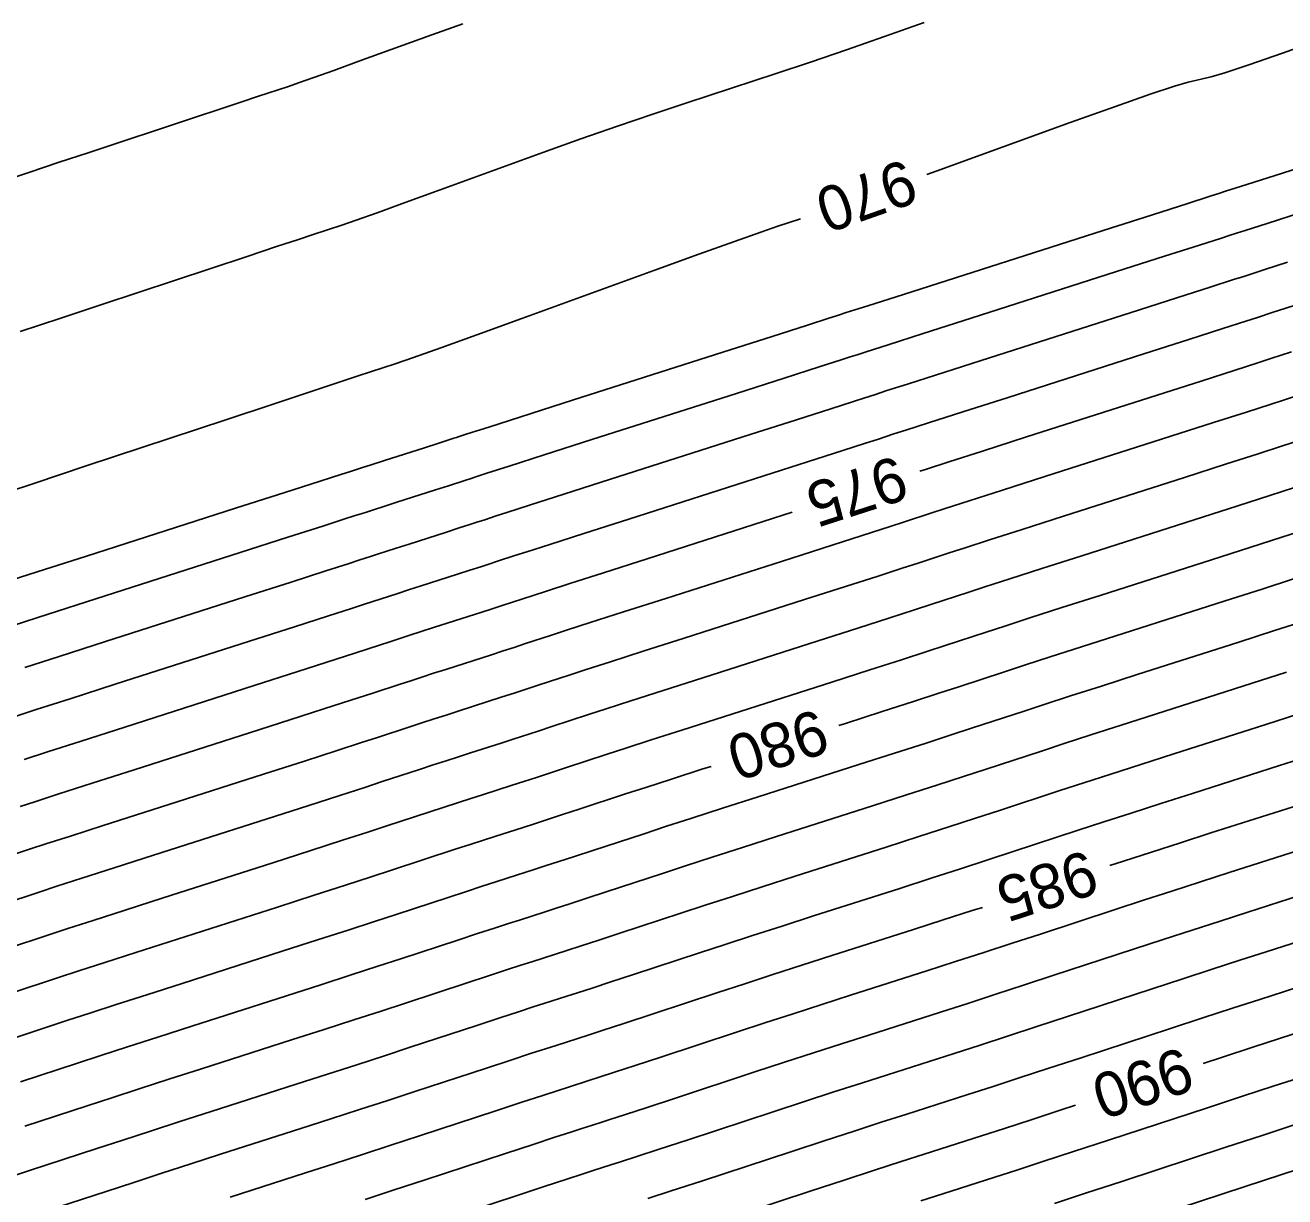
# Model space of a CAD drawing. Extents: x 2175772 to 2185556, y 721391 to 722853.
# Drawn here: x 2178902 to 2178980.9, y 721896.5 to 721969.8 of the extents above; entities that cross this region are included whole.
import ezdxf

# ---------------------------------------------------------------- set-up
doc = ezdxf.new("R2010")
doc.units = 0
doc.layers.add('DT_X_Contour_Major', color=7, linetype='Continuous')
doc.layers.add('DT_X_Contour_Minor', color=7, linetype='Continuous')

msp = doc.modelspace()

# ---------------------------------------------------------------- linework, layer by layer
at = {"layer": 'DT_X_Contour_Major'}
for points in [[(2178958.479, 721960.501), (2178959.055, 721960.709), (2178967.461, 721963.751), (2178970.287, 721964.765), (2178972.46, 721965.525), (2178973.98, 721966.032), (2178974.847, 721966.285), (2178976.29, 721966.623), (2178977.147, 721966.871), (2178978.636, 721967.362), (2178980.756, 721968.095), (2178983.507, 721969.072)], [(2178895.939, 721938.964), (2178902.542, 721941.15), (2178905.826, 721942.238), (2178914.565, 721945.131), (2178917.541, 721946.117), (2178919.915, 721946.903), (2178922.857, 721947.877), (2178925.175, 721948.644), (2178926.323, 721949.037), (2178928.03, 721949.64), (2178930.294, 721950.454), (2178933.117, 721951.478), (2178941.388, 721954.488), (2178944.199, 721955.507), (2178946.428, 721956.307), (2178948.074, 721956.888), (2178949.139, 721957.25), (2178950.556, 721957.712)], [(2178958.045, 721941.917), (2178958.393, 721942.029), (2178959.859, 721942.501), (2178961.967, 721943.177), (2178964.718, 721944.058), (2178972.909, 721946.678), (2178975.657, 721947.558), (2178979.214, 721948.7), (2178980.023, 721948.963), (2178981.318, 721949.388)], [(2178901.934, 721923.862), (2178903.409, 721924.338), (2178905.51, 721925.013), (2178908.24, 721925.889), (2178916.354, 721928.49), (2178919.082, 721929.365), (2178922.652, 721930.514), (2178923.493, 721930.787), (2178924.898, 721931.248), (2178925.461, 721931.432), (2178926.096, 721931.638), (2178926.804, 721931.867), (2178927.583, 721932.117), (2178929.759, 721932.815), (2178930.538, 721933.065), (2178931.243, 721933.292), (2178931.874, 721933.497), (2178933.82, 721934.135), (2178934.657, 721934.407), (2178936.127, 721934.88), (2178938.231, 721935.555), (2178940.969, 721936.431), (2178950.051, 721939.338)], [(2178952.958, 721925.987), (2178953.371, 721926.119), (2178955.678, 721926.858), (2178957.632, 721927.487), (2178959.233, 721928.005), (2178960.482, 721928.412), (2178963.343, 721929.351), (2178964.594, 721929.759), (2178966.202, 721930.279), (2178968.168, 721930.911), (2178977.158, 721933.789), (2178979.478, 721934.532), (2178981.437, 721935.162)], [(2178901.12, 721909.223), (2178904.086, 721910.197), (2178905.368, 721910.615), (2178906.987, 721911.14), (2178908.946, 721911.771), (2178917.817, 721914.616), (2178920.112, 721915.353), (2178922.066, 721915.983), (2178923.68, 721916.505), (2178924.953, 721916.921), (2178928.942, 721918.23), (2178929.88, 721918.535), (2178930.707, 721918.804), (2178931.424, 721919.035), (2178933.19, 721919.601), (2178933.905, 721919.831), (2178934.728, 721920.098), (2178935.658, 721920.402), (2178936.695, 721920.741), (2178939.605, 721921.696), (2178940.869, 721922.109), (2178942.482, 721922.63), (2178944.443, 721923.261), (2178944.958, 721923.426)], [(2178981.408, 721920.9), (2178976.262, 721919.253), (2178974.368, 721918.645), (2178972.546, 721918.057), (2178970.796, 721917.489), (2178969.936, 721917.208)], [(2178961.953, 721914.595), (2178961.318, 721914.388), (2178959.508, 721913.804), (2178957.63, 721913.202), (2178952.534, 721911.571), (2178950.654, 721910.968), (2178948.837, 721910.381), (2178947.082, 721909.811), (2178945.39, 721909.257), (2178939.442, 721907.306), (2178938.213, 721906.904), (2178937.273, 721906.598), (2178936.62, 721906.387), (2178935.265, 721905.952), (2178933.663, 721905.432), (2178932.423, 721905.027), (2178930.891, 721904.524), (2178926.414, 721903.055), (2178924.709, 721902.497), (2178922.951, 721901.926), (2178921.142, 721901.341), (2178919.279, 721900.742), (2178914.244, 721899.128), (2178912.381, 721898.529), (2178910.566, 721897.942), (2178908.801, 721897.368), (2178907.086, 721896.807), (2178902.576, 721895.326)], [(2178982.034, 721906.851), (2178980.568, 721906.38), (2178978.889, 721905.836), (2178976.997, 721905.219), (2178975.777, 721904.819)], [(2178967.795, 721902.201), (2178966.889, 721901.904), (2178965.004, 721901.29), (2178963.337, 721900.75), (2178961.889, 721900.284), (2178958.317, 721899.141), (2178956.866, 721898.674), (2178955.192, 721898.132), (2178953.295, 721897.513), (2178951.175, 721896.819), (2178945.224, 721894.866)]]:
    msp.add_lwpolyline(points, dxfattribs=at)
at = {"layer": 'DT_X_Contour_Minor'}
for points in [[(2178900.456, 721960.043), (2178902.295, 721960.652), (2178904.128, 721961.259), (2178905.954, 721961.863), (2178912.615, 721964.069), (2178914.264, 721964.615), (2178915.58, 721965.05), (2178916.562, 721965.376), (2178917.21, 721965.59), (2178918.494, 721966.015), (2178919.13, 721966.233), (2178920.076, 721966.567), (2178921.331, 721967.018), (2178922.894, 721967.585), (2178927.477, 721969.253), (2178929.408, 721969.94)], [(2178901.688, 721950.659), (2178904.248, 721951.507), (2178906.799, 721952.352), (2178915.903, 721955.366), (2178917.747, 721955.977), (2178919.124, 721956.432), (2178920.034, 721956.734), (2178921.835, 721957.33), (2178922.727, 721957.635), (2178924.053, 721958.104), (2178925.812, 721958.736), (2178928.006, 721959.531), (2178934.433, 721961.87), (2178936.804, 721962.723), (2178939.096, 721963.528), (2178941.31, 721964.284), (2178943.446, 721964.992), (2178949.037, 721966.816), (2178951.189, 721967.529), (2178953.453, 721968.301), (2178955.827, 721969.132), (2178958.314, 721970.023)], [(2178900.545, 721934.896), (2178902.762, 721935.607), (2178905.838, 721936.593), (2178915.184, 721939.589), (2178918.258, 721940.575), (2178920.474, 721941.286), (2178921.829, 721941.72), (2178922.325, 721941.88), (2178922.501, 721941.938), (2178923.07, 721942.121), (2178923.681, 721942.317), (2178924.511, 721942.583), (2178927.014, 721943.386), (2178927.843, 721943.651), (2178928.846, 721943.974), (2178929.02, 721944.03), (2178929.192, 721944.086), (2178929.687, 721944.245), (2178931.044, 721944.679), (2178936.343, 721946.375), (2178945.706, 721949.371), (2178948.784, 721950.356), (2178950.996, 721951.064), (2178952.343, 721951.495), (2178952.823, 721951.649), (2178952.949, 721951.691), (2178953.431, 721951.846), (2178954.784, 721952.279), (2178957.007, 721952.99), (2178969.509, 721956.99), (2178972.6, 721957.979), (2178974.817, 721958.688), (2178976.159, 721959.118), (2178976.626, 721959.268), (2178976.707, 721959.294), (2178977.177, 721959.445), (2178978.525, 721959.876), (2178980.752, 721960.589), (2178983.858, 721961.582)], [(2178901.261, 721932.256), (2178903.449, 721932.958), (2178906.438, 721933.917), (2178915.476, 721936.814), (2178918.464, 721937.773), (2178920.651, 721938.474), (2178922.035, 721938.919), (2178922.617, 721939.107), (2178923.101, 721939.265), (2178923.373, 721939.354), (2178923.827, 721939.5), (2178924.462, 721939.704), (2178925.279, 721939.967), (2178927.7, 721940.743), (2178928.517, 721941.005), (2178929.603, 721941.354), (2178929.873, 721941.442), (2178930.349, 721941.598), (2178930.929, 721941.785), (2178932.315, 721942.229), (2178934.505, 721942.931), (2178937.499, 721943.889), (2178946.558, 721946.788), (2178949.55, 721947.746), (2178951.734, 721948.445), (2178953.108, 721948.885), (2178953.674, 721949.068), (2178954.104, 721949.209), (2178954.672, 721949.392), (2178956.053, 721949.834), (2178958.247, 721950.537), (2178961.255, 721951.499), (2178970.359, 721954.412), (2178973.364, 721955.374), (2178975.552, 721956.074), (2178976.923, 721956.513), (2178977.475, 721956.691), (2178977.86, 721956.817), (2178978.415, 721956.996), (2178979.792, 721957.437), (2178981.99, 721958.141)], [(2178901.977, 721929.617), (2178904.136, 721930.31), (2178907.039, 721931.241), (2178915.769, 721934.04), (2178918.67, 721934.97), (2178920.828, 721935.663), (2178922.241, 721936.117), (2178922.909, 721936.333), (2178923.7, 721936.593), (2178924.069, 721936.713), (2178924.583, 721936.88), (2178925.243, 721937.092), (2178926.047, 721937.35), (2178928.386, 721938.1), (2178929.19, 721938.358), (2178929.848, 721938.57), (2178930.36, 721938.735), (2178930.726, 721938.854), (2178931.506, 721939.11), (2178932.172, 721939.326), (2178933.586, 721939.78), (2178935.747, 721940.472), (2178938.656, 721941.403), (2178947.409, 721944.204), (2178950.316, 721945.135), (2178952.471, 721945.825), (2178953.874, 721946.275), (2178954.525, 721946.486), (2178955.259, 721946.726), (2178955.912, 721946.937), (2178957.321, 721947.39), (2178962.409, 721949.019), (2178971.209, 721951.834), (2178974.129, 721952.769), (2178976.288, 721953.46), (2178977.686, 721953.909), (2178978.325, 721954.115), (2178979.012, 721954.341), (2178979.653, 721954.548), (2178981.058, 721954.998)], [(2178901.247, 721926.512), (2178902.693, 721926.977), (2178904.823, 721927.661), (2178907.639, 721928.565), (2178916.061, 721931.265), (2178918.876, 721932.168), (2178921.005, 721932.851), (2178922.446, 721933.315), (2178923.201, 721933.56), (2178924.299, 721933.921), (2178924.765, 721934.073), (2178925.34, 721934.259), (2178926.023, 721934.479), (2178926.815, 721934.734), (2178929.073, 721935.457), (2178929.864, 721935.711), (2178930.545, 721935.931), (2178931.117, 721936.116), (2178931.578, 721936.267), (2178932.663, 721936.623), (2178933.414, 721936.866), (2178934.856, 721937.33), (2178936.989, 721938.013), (2178939.812, 721938.917), (2178948.261, 721941.621), (2178953.208, 721943.205), (2178954.639, 721943.665), (2178955.376, 721943.904), (2178956.414, 721944.244), (2178957.152, 721944.483), (2178958.59, 721944.945), (2178960.727, 721945.63), (2178963.563, 721946.538), (2178972.059, 721949.256), (2178974.893, 721950.163), (2178977.023, 721950.846), (2178978.45, 721951.305), (2178979.174, 721951.539), (2178980.165, 721951.864), (2178980.891, 721952.099), (2178982.324, 721952.56)], [(2178901.687, 721920.909), (2178902.621, 721921.213), (2178904.124, 721921.698), (2178906.197, 721922.365), (2178908.84, 721923.212), (2178916.646, 721925.715), (2178919.288, 721926.563), (2178921.359, 721927.228), (2178922.858, 721927.712), (2178923.785, 721928.014), (2178925.498, 721928.576), (2178926.157, 721928.792), (2178926.853, 721929.018), (2178927.585, 721929.254), (2178928.352, 721929.501), (2178931.211, 721930.418), (2178931.94, 721930.653), (2178932.631, 721930.878), (2178933.284, 721931.092), (2178934.977, 721931.647), (2178935.899, 721931.947), (2178937.398, 721932.43), (2178939.474, 721933.096), (2178942.125, 721933.945), (2178949.965, 721936.454), (2178952.614, 721937.302), (2178956.171, 721938.445), (2178957.078, 721938.74), (2178958.723, 721939.28), (2178959.633, 721939.575), (2178961.128, 721940.057), (2178963.207, 721940.724), (2178965.872, 721941.577), (2178973.759, 721944.101), (2178976.421, 721944.953), (2178978.495, 721945.618), (2178979.978, 721946.096), (2178980.872, 721946.386), (2178982.471, 721946.911)], [(2178900.246, 721917.561), (2178902.287, 721918.231), (2178903.307, 721918.563), (2178904.84, 721919.058), (2178906.884, 721919.716), (2178909.441, 721920.536), (2178916.939, 721922.94), (2178919.494, 721923.76), (2178921.536, 721924.417), (2178923.063, 721924.91), (2178924.077, 721925.241), (2178926.097, 721925.903), (2178926.854, 721926.151), (2178927.61, 721926.397), (2178928.365, 721926.642), (2178929.12, 721926.884), (2178931.885, 721927.771), (2178932.637, 721928.015), (2178933.388, 721928.259), (2178934.137, 721928.504), (2178936.134, 721929.159), (2178937.142, 721929.487), (2178938.669, 721929.98), (2178940.716, 721930.637), (2178943.282, 721931.459), (2178950.816, 721933.87), (2178953.38, 721934.691), (2178955.42, 721935.346), (2178956.936, 721935.835), (2178957.929, 721936.158), (2178959.878, 721936.798), (2178960.873, 721937.121), (2178962.396, 721937.612), (2178964.447, 721938.271), (2178967.027, 721939.097), (2178974.609, 721941.523), (2178977.186, 721942.348), (2178979.23, 721943.004), (2178980.742, 721943.492), (2178981.722, 721943.81)], [(2178900.538, 721914.782), (2178902.886, 721915.553), (2178903.994, 721915.914), (2178905.556, 721916.419), (2178907.571, 721917.068), (2178910.041, 721917.86), (2178919.7, 721920.958), (2178921.712, 721921.606), (2178923.269, 721922.109), (2178924.369, 721922.467), (2178926.696, 721923.231), (2178927.55, 721923.511), (2178928.366, 721923.777), (2178929.146, 721924.029), (2178929.888, 721924.268), (2178931.817, 721924.886), (2178932.558, 721925.125), (2178934.144, 721925.64), (2178934.99, 721925.917), (2178937.291, 721926.672), (2178938.384, 721927.028), (2178939.94, 721927.53), (2178941.958, 721928.179), (2178944.438, 721928.973), (2178951.668, 721931.287), (2178954.146, 721932.08), (2178956.157, 721932.726), (2178957.702, 721933.225), (2178958.78, 721933.576), (2178961.033, 721934.315), (2178962.113, 721934.667), (2178963.665, 721935.168), (2178965.687, 721935.818), (2178968.181, 721936.616), (2178977.95, 721939.743), (2178979.966, 721940.39), (2178981.506, 721940.887)], [(2178900.829, 721912.003), (2178903.486, 721912.875), (2178904.681, 721913.265), (2178906.272, 721913.779), (2178908.259, 721914.419), (2178910.641, 721915.184), (2178917.524, 721917.391), (2178919.906, 721918.155), (2178921.889, 721918.794), (2178923.475, 721919.307), (2178924.661, 721919.694), (2178927.295, 721920.559), (2178928.246, 721920.87), (2178929.926, 721921.416), (2178930.656, 721921.651), (2178932.503, 721922.244), (2178933.232, 721922.478), (2178934.031, 721922.737), (2178934.901, 721923.021), (2178935.843, 721923.329), (2178938.448, 721924.184), (2178939.627, 721924.568), (2178941.211, 721925.08), (2178943.201, 721925.72), (2178952.52, 721928.703), (2178954.912, 721929.469), (2178956.894, 721930.107), (2178958.467, 721930.615), (2178959.631, 721930.994), (2178962.188, 721931.833), (2178963.354, 721932.213), (2178964.934, 721932.724), (2178966.927, 721933.365), (2178969.335, 721934.136), (2178976.308, 721936.367), (2178978.714, 721937.138), (2178980.701, 721937.776), (2178982.27, 721938.283)], [(2178901.411, 721906.444), (2178904.686, 721907.519), (2178906.054, 721907.966), (2178907.703, 721908.5), (2178909.633, 721909.122), (2178911.842, 721909.832), (2178918.109, 721911.841), (2178920.318, 721912.55), (2178922.243, 721913.171), (2178923.886, 721913.704), (2178925.246, 721914.148), (2178928.494, 721915.214), (2178929.638, 721915.589), (2178930.636, 721915.915), (2178931.488, 721916.191), (2178932.192, 721916.418), (2178933.876, 721916.958), (2178934.579, 721917.185), (2178935.425, 721917.459), (2178936.415, 721917.782), (2178937.548, 721918.154), (2178940.762, 721919.208), (2178942.112, 721919.649), (2178943.753, 721920.181), (2178945.685, 721920.803), (2178947.908, 721921.515), (2178954.223, 721923.536), (2178956.444, 721924.248), (2178958.369, 721924.867), (2178959.999, 721925.395), (2178961.333, 721925.83), (2178964.498, 721926.869), (2178965.834, 721927.305), (2178967.471, 721927.835), (2178969.408, 721928.458), (2178971.644, 721929.175), (2178978.008, 721931.211), (2178980.243, 721931.927), (2178982.172, 721932.548)], [(2178901.703, 721903.664), (2178905.286, 721904.841), (2178906.741, 721905.316), (2178908.419, 721905.861), (2178910.32, 721906.474), (2178912.443, 721907.156), (2178920.524, 721909.748), (2178922.42, 721910.36), (2178924.092, 721910.902), (2178925.538, 721911.375), (2178929.093, 721912.542), (2178930.335, 721912.949), (2178931.393, 721913.294), (2178932.268, 721913.579), (2178932.96, 721913.802), (2178934.562, 721914.315), (2178935.252, 721914.538), (2178936.122, 721914.821), (2178937.172, 721915.163), (2178938.401, 721915.566), (2178941.919, 721916.721), (2178943.354, 721917.19), (2178945.024, 721917.731), (2178946.927, 721918.344), (2178949.064, 721919.029), (2178955.075, 721920.952), (2178957.21, 721921.637), (2178959.106, 721922.248), (2178960.764, 721922.785), (2178962.184, 721923.248), (2178965.653, 721924.387), (2178967.075, 721924.851), (2178968.74, 721925.39), (2178970.648, 721926.005), (2178972.799, 721926.694), (2178978.858, 721928.633), (2178981.007, 721929.322)], [(2178901.994, 721900.885), (2178905.886, 721902.163), (2178907.428, 721902.667), (2178909.135, 721903.221), (2178911.007, 721903.825), (2178913.043, 721904.48), (2178918.694, 721906.292), (2178920.73, 721906.946), (2178922.597, 721907.548), (2178924.297, 721908.1), (2178925.83, 721908.601), (2178929.692, 721909.869), (2178931.031, 721910.308), (2178932.15, 721910.674), (2178933.049, 721910.966), (2178933.729, 721911.185), (2178935.926, 721911.891), (2178936.819, 721912.182), (2178937.929, 721912.544), (2178939.254, 721912.979), (2178943.076, 721914.233), (2178944.597, 721914.73), (2178946.295, 721915.281), (2178948.17, 721915.885), (2178950.221, 721916.543), (2178955.927, 721918.369), (2178957.976, 721919.026), (2178959.843, 721919.628), (2178961.53, 721920.175), (2178963.035, 721920.667), (2178966.807, 721921.905), (2178968.315, 721922.397), (2178970.008, 721922.946), (2178971.888, 721923.552), (2178973.953, 721924.214), (2178979.708, 721926.055), (2178981.771, 721926.717)], [(2178982.535, 721924.112), (2178980.558, 721923.477), (2178975.107, 721921.734), (2178973.128, 721921.099), (2178971.277, 721920.502), (2178969.555, 721919.943), (2178967.962, 721919.422), (2178963.886, 721918.085), (2178962.295, 721917.565), (2178960.581, 721917.008), (2178958.742, 721916.415), (2178956.778, 721915.785), (2178951.378, 721914.057), (2178949.412, 721913.426), (2178947.566, 721912.831), (2178945.839, 721912.271), (2178944.233, 721911.745), (2178940.107, 721910.391), (2178938.686, 721909.925), (2178937.516, 721909.543), (2178936.599, 721909.244), (2178935.934, 721909.03), (2178934.497, 721908.569), (2178933.83, 721908.354), (2178932.906, 721908.053), (2178931.727, 721907.667), (2178930.291, 721907.197), (2178926.122, 721905.828), (2178924.503, 721905.299), (2178922.774, 721904.737), (2178920.936, 721904.143), (2178918.987, 721903.517), (2178913.644, 721901.804), (2178911.694, 721901.177), (2178909.851, 721900.582), (2178908.115, 721900.018), (2178906.486, 721899.485), (2178902.285, 721898.106), (2178900.658, 721897.573)], [(2178982.258, 721918.322), (2178977.416, 721916.773), (2178975.608, 721916.192), (2178973.815, 721915.613), (2178972.036, 721915.035), (2178970.272, 721914.458), (2178965.588, 721912.921), (2178963.827, 721912.345), (2178962.055, 721911.769), (2178960.274, 721911.193), (2178958.482, 721910.618), (2178953.691, 721909.085), (2178951.897, 721908.509), (2178950.108, 721907.931), (2178948.325, 721907.351), (2178946.547, 721906.77), (2178941.812, 721905.216), (2178940.199, 721904.687), (2178938.911, 721904.265), (2178937.946, 721903.951), (2178937.307, 721903.744), (2178936.033, 721903.336), (2178935.391, 721903.128), (2178934.42, 721902.812), (2178933.119, 721902.386), (2178931.49, 721901.852), (2178926.706, 721900.282), (2178924.914, 721899.695), (2178923.128, 721899.114), (2178921.347, 721898.538), (2178919.572, 721897.967), (2178914.845, 721896.452)], [(2178983.108, 721915.744), (2178978.571, 721914.292), (2178976.848, 721913.739), (2178975.083, 721913.169), (2178973.276, 721912.581), (2178971.427, 721911.976), (2178966.439, 721910.339), (2178964.592, 721909.735), (2178962.792, 721909.149), (2178961.039, 721908.582), (2178959.334, 721908.035), (2178954.847, 721906.599), (2178953.139, 721906.05), (2178951.379, 721905.481), (2178949.567, 721904.892), (2178947.704, 721904.282), (2178942.665, 721902.628), (2178940.956, 721902.068), (2178939.608, 721901.626), (2178938.62, 721901.304), (2178937.993, 721901.102), (2178936.801, 721900.719), (2178936.172, 721900.516), (2178935.176, 721900.191), (2178933.815, 721899.746), (2178932.089, 721899.18), (2178926.998, 721897.508), (2178925.12, 721896.894), (2178923.305, 721896.303)], [(2178983.958, 721913.166), (2178979.725, 721911.812), (2178978.088, 721911.286), (2178976.352, 721910.724), (2178974.516, 721910.127), (2178972.582, 721909.494), (2178967.29, 721907.757), (2178965.358, 721907.124), (2178963.53, 721906.529), (2178961.805, 721905.971), (2178960.185, 721905.451), (2178956.004, 721904.113), (2178954.381, 721903.592), (2178952.65, 721903.031), (2178950.81, 721902.432), (2178948.861, 721901.794), (2178943.518, 721900.041), (2178941.713, 721899.449), (2178940.305, 721898.988), (2178939.293, 721898.658), (2178938.679, 721898.459), (2178937.569, 721898.103), (2178936.952, 721897.903), (2178935.933, 721897.571), (2178934.512, 721897.105), (2178932.688, 721896.507), (2178927.29, 721894.735)], [(2178984.808, 721910.588), (2178980.879, 721909.331), (2178979.328, 721908.833), (2178977.621, 721908.28), (2178975.757, 721907.673), (2178973.737, 721907.011), (2178968.141, 721905.175), (2178966.123, 721904.514), (2178964.267, 721903.91), (2178962.571, 721903.361), (2178961.037, 721902.867), (2178957.16, 721901.627), (2178955.623, 721901.133), (2178953.921, 721900.582), (2178952.052, 721899.973), (2178950.018, 721899.306), (2178944.371, 721897.453), (2178942.47, 721896.83), (2178941.002, 721896.349)], [(2178981.808, 721903.926), (2178980.158, 721903.391), (2178978.237, 721902.765), (2178976.046, 721902.047), (2178969.843, 721900.011), (2178967.655, 721899.294), (2178965.741, 721898.67), (2178964.103, 721898.139), (2178962.74, 721897.7), (2178959.473, 721896.655), (2178958.108, 721896.216)], [(2178981.427, 721900.947), (2178979.478, 721900.311), (2178977.201, 721899.565), (2178970.694, 721897.429), (2178968.42, 721896.684), (2178966.479, 721896.05)], [(2178982.695, 721898.502), (2178980.718, 721897.857), (2178978.356, 721897.083), (2178971.545, 721894.847)]]:
    msp.add_lwpolyline(points, dxfattribs=at)

# ---------------------------------------------------------------- texts
at = {"layer": 'DT_X_Contour_Major'}
for s, rotation, p in [('970', 199.39495, (2178957.181, 721961.5)), ('975', 197.87957, (2178956.652, 721942.93)), ('980', 197.74972, (2178951.701, 721927.055)), ('985', 198.12532, (2178968.558, 721918.228)), ('990', 198.15956, (2178974.534, 721905.885))]:
    msp.add_text(s, height=2.8, rotation=rotation, dxfattribs=at).set_placement(p)

doc.saveas('drawing.dxf')
